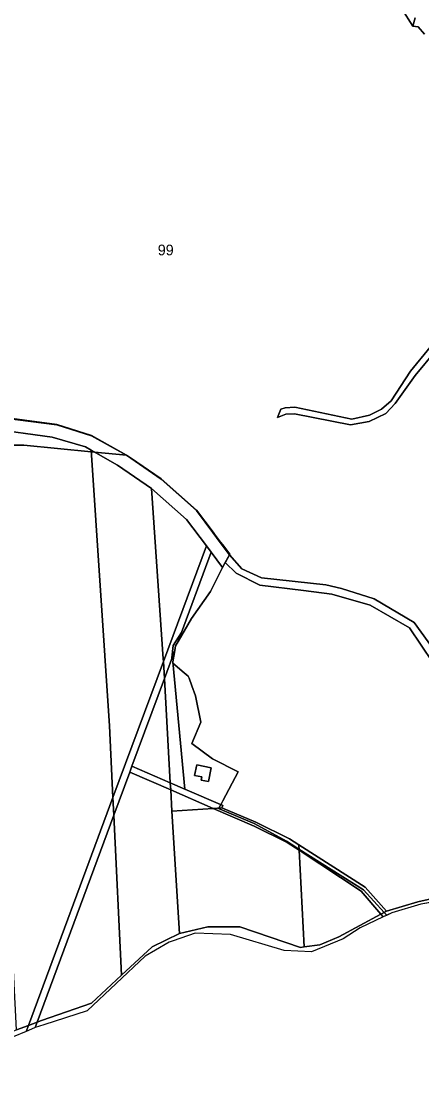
# Model space of a CAD drawing. Extents: x -522079 to -518833, y -1142400 to -1139961.
# Drawn here: x -519379.4 to -519191.9, y -1141869.9 to -1141371.1 of the extents above; entities that cross this region are included whole.
import ezdxf

# ---------------------------------------------------------------- set-up
doc = ezdxf.new("R2010")
doc.units = 0
for name, color, linetype in [('95560013', 7, 'Continuous'), ('95610013', 7, 'Continuous'), ('95620013', 7, 'Continuous'), ('95630013', 7, 'Continuous'), ('95640013', 7, 'Continuous'), ('95660013', 7, 'Continuous')]:
    doc.layers.add(name, color=color, linetype=linetype)

msp = doc.modelspace()

# ---------------------------------------------------------------- linework, layer by layer
at = {"layer": '95560013'}
for points in [[(-519338.11, -1141700.9), (-519336.47, -1141734.52), (-519376.07, -1141841.19), (-519381.7, -1141843.28), (-519389.39, -1141692.08), (-519397.82, -1141561.07), (-519394.67, -1141561.74), (-519364.95, -1141565.79), (-519349.35, -1141570.28), (-519346.66, -1141571.83)], [(-519312.91, -1141669.62), (-519312.84, -1141670.86), (-519336.47, -1141734.52), (-519338.11, -1141700.9), (-519346.66, -1141571.83), (-519334.38, -1141578.92), (-519318.43, -1141589.84)], [(-519318.43, -1141589.84), (-519301.98, -1141604.24), (-519292.71, -1141616.64), (-519312.84, -1141670.86), (-519312.91, -1141669.62)], [(-519305.24, -1141798.22), (-519318.06, -1141804.43), (-519332.42, -1141817.72), (-519336.07, -1141742.78), (-519328.61, -1141722.63), (-519309.44, -1141730.94), (-519308.88, -1141740.9)], [(-519289.52, -1141739.58), (-519308.88, -1141740.9), (-519309.44, -1141730.94)], [(-519254.9, -1141755.61), (-519249.34, -1141759.14), (-519246.92, -1141804.45), (-519248.63, -1141804.68), (-519277.03, -1141795.09), (-519292.12, -1141794.98), (-519305.24, -1141798.22), (-519308.88, -1141740.9), (-519289.52, -1141739.58), (-519270.39, -1141747.88)], [(-519336.07, -1141742.78), (-519332.42, -1141817.72), (-519346.6, -1141830.84), (-519369.96, -1141838.92), (-519371.92, -1141839.65)], [(-519220.27, -1141778.33), (-519211, -1141789.08), (-519230.77, -1141799.67), (-519239.54, -1141803.44), (-519246.92, -1141804.45), (-519249.34, -1141759.14)], [(-519243.51, -1141806.68), (-519256.37, -1141806.05), (-519281.47, -1141798.57), (-519297.93, -1141798.04), (-519308.25, -1141801.56), (-519310.14, -1141802.21), (-519316.53, -1141805.97), (-519321.4, -1141808.82), (-519348.63, -1141834.32), (-519368.78, -1141840.86), (-519372.86, -1141842.19), (-519371.92, -1141839.65), (-519369.96, -1141838.92), (-519346.6, -1141830.84), (-519332.42, -1141817.72), (-519318.06, -1141804.43), (-519305.24, -1141798.22), (-519292.12, -1141794.98), (-519277.03, -1141795.09), (-519248.63, -1141804.68), (-519246.92, -1141804.45), (-519239.54, -1141803.44), (-519230.77, -1141799.67), (-519211, -1141789.08), (-519209.88, -1141790.38), (-519220.64, -1141795.43), (-519228.74, -1141800.67)], [(-519389.29, -1141849.01), (-519391.5, -1141849.93), (-519408.1, -1141868.36), (-519409.46, -1141869.87), (-519458.26, -1141842.83), (-519448.38, -1141847.58), (-519430.66, -1141856.11), (-519410.94, -1141866.01), (-519388.28, -1141845.72), (-519381.7, -1141843.28), (-519376.07, -1141841.19), (-519377.1, -1141843.96)]]:
    msp.add_lwpolyline(points, close=True, dxfattribs=at)
at = {"layer": '95610013'}
for points in [[(-519290.49, -1141619.61), (-519285.15, -1141626.73), (-519290.81, -1141638.01), (-519299.72, -1141650.6), (-519305.95, -1141661.39)], [(-519308.5, -1141671.02), (-519302.86, -1141730.53), (-519309.63, -1141727.6), (-519312.39, -1141678.8), (-519307.53, -1141665.67)], [(-519309.63, -1141727.6), (-519327.57, -1141719.82), (-519312.39, -1141678.8)]]:
    msp.add_lwpolyline(points, close=True, dxfattribs=at)
at = {"layer": '95620013'}
for points in [[(-519201.22, -1141365.24), (-519195.98, -1141373.38), (-519193.48, -1141373.59), (-519190.53, -1141377.07)], [(-519187.98, -1141523.67), (-519197.16, -1141534.83), (-519206.19, -1141548.7), (-519210.78, -1141552.72), (-519216.28, -1141555.43), (-519224.64, -1141557.32), (-519251.3, -1141551.66), (-519255.9, -1141551.98), (-519257.81, -1141552.73), (-519259.41, -1141556.52), (-519255.57, -1141555.02), (-519251.39, -1141554.86), (-519225.22, -1141560.03), (-519216.52, -1141558.38), (-519208.65, -1141554.69), (-519204.3, -1141549.93), (-519194.87, -1141536.97), (-519185.11, -1141524.98)], [(-519185.55, -1141666.07), (-519195.4, -1141652.58), (-519214.22, -1141641.4), (-519229.49, -1141636.68), (-519236.73, -1141634.83), (-519266.93, -1141631.65), (-519276.07, -1141627.44), (-519281.83, -1141620.82), (-519286.19, -1141615.06), (-519289.76, -1141610.43), (-519297.36, -1141600.15), (-519313.9, -1141585.4), (-519330.14, -1141574.2), (-519346.5, -1141565.05), (-519362.75, -1141559.82), (-519393.2, -1141555.81)], [(-519181.21, -1141780.54), (-519193.63, -1141783.33), (-519208.31, -1141787.64), (-519218.36, -1141776.45), (-519249.47, -1141756.69), (-519253.85, -1141753.9), (-519269.54, -1141746.07), (-519285.49, -1141739.31), (-519284.96, -1141738.29), (-519302.86, -1141730.53), (-519308.5, -1141671.02), (-519307.53, -1141665.67), (-519307.13, -1141663.43), (-519305.95, -1141661.39), (-519299.72, -1141650.6), (-519290.81, -1141638.01), (-519285.15, -1141626.73), (-519283.88, -1141624.46), (-519278.79, -1141629.39), (-519267.72, -1141635.03), (-519247.24, -1141637.55), (-519234.03, -1141639.34), (-519215.97, -1141644.42), (-519197.57, -1141654.98), (-519170.28, -1141695.6)]]:
    msp.add_lwpolyline(points, dxfattribs=at)
msp.add_lwpolyline([(-519297.27, -1141719.22), (-519298.29, -1141724.1), (-519294.81, -1141724.84), (-519295.11, -1141726.32), (-519291.74, -1141727), (-519290.41, -1141720.65)], close=True, dxfattribs=at)
at = {"layer": '95630013'}
for points in [[(-519194.96, -1141369.43), (-519195.98, -1141373.38), (-519201.22, -1141365.24)], [(-519190.53, -1141377.07), (-519193.48, -1141373.59), (-519195.98, -1141373.38), (-519194.96, -1141369.43)]]:
    msp.add_lwpolyline(points, dxfattribs=at)
at = {"layer": '95640013'}
for points in [[(-519185.11, -1141524.98), (-519194.87, -1141536.97), (-519204.3, -1141549.93), (-519208.65, -1141554.69), (-519216.52, -1141558.38), (-519225.22, -1141560.03), (-519251.39, -1141554.86), (-519255.57, -1141555.02), (-519259.41, -1141556.52), (-519257.81, -1141552.73), (-519255.9, -1141551.98), (-519251.3, -1141551.66), (-519224.64, -1141557.32), (-519216.28, -1141555.43), (-519210.78, -1141552.72), (-519206.19, -1141548.7), (-519197.16, -1141534.83), (-519187.98, -1141523.67)], [(-519393.2, -1141555.81), (-519362.75, -1141559.82), (-519346.5, -1141565.05), (-519330.14, -1141574.2), (-519313.9, -1141585.4), (-519297.36, -1141600.15), (-519289.76, -1141610.43), (-519286.19, -1141615.06), (-519281.83, -1141620.82), (-519283.88, -1141624.46), (-519285.15, -1141626.73), (-519290.49, -1141619.61), (-519292.71, -1141616.64), (-519301.98, -1141604.24), (-519318.43, -1141589.84), (-519334.38, -1141578.92), (-519346.66, -1141571.83), (-519349.35, -1141570.28), (-519364.95, -1141565.79), (-519394.67, -1141561.74)]]:
    msp.add_lwpolyline(points, dxfattribs=at)
for points in [[(-519292.71, -1141616.64), (-519290.49, -1141619.61), (-519305.95, -1141661.39), (-519307.13, -1141663.43), (-519307.53, -1141665.67), (-519312.39, -1141678.8), (-519312.84, -1141670.86)], [(-519215.97, -1141644.42), (-519234.03, -1141639.34), (-519247.24, -1141637.55), (-519267.72, -1141635.03), (-519278.79, -1141629.39), (-519283.88, -1141624.46), (-519281.83, -1141620.82), (-519276.07, -1141627.44), (-519266.93, -1141631.65), (-519236.73, -1141634.83), (-519229.49, -1141636.68), (-519214.22, -1141641.4), (-519195.4, -1141652.58), (-519185.55, -1141666.07), (-519168.83, -1141692.07), (-519157.76, -1141703.36), (-519119.77, -1141724.36), (-519107.07, -1141732.42), (-519111.34, -1141734.71), (-519122.24, -1141726.88), (-519160.32, -1141706.01), (-519170.28, -1141695.6), (-519197.57, -1141654.98)], [(-519312.39, -1141678.8), (-519327.57, -1141719.82), (-519328.61, -1141722.63), (-519336.07, -1141742.78), (-519336.47, -1141734.52), (-519312.84, -1141670.86)], [(-519298.29, -1141724.1), (-519297.27, -1141719.22), (-519290.41, -1141720.65), (-519291.74, -1141727), (-519295.11, -1141726.32), (-519294.81, -1141724.84)], [(-519309.44, -1141730.94), (-519328.61, -1141722.63), (-519327.57, -1141719.82), (-519309.63, -1141727.6)], [(-519285.49, -1141739.31), (-519289.52, -1141739.58), (-519309.44, -1141730.94), (-519309.63, -1141727.6), (-519302.86, -1141730.53), (-519284.96, -1141738.29)], [(-519336.47, -1141734.52), (-519336.07, -1141742.78), (-519371.92, -1141839.65), (-519376.07, -1141841.19)], [(-519192.31, -1141784.44), (-519205.85, -1141788.49), (-519209.88, -1141790.38), (-519211, -1141789.08), (-519208.31, -1141787.64), (-519193.63, -1141783.33), (-519181.21, -1141780.54), (-519173.18, -1141777.23), (-519164.17, -1141772.59), (-519130.56, -1141747.22), (-519111.34, -1141734.71), (-519107.07, -1141732.42), (-519106.29, -1141740.33), (-519117.64, -1141741.85), (-519132.98, -1141750.7), (-519141.38, -1141757.45), (-519162.82, -1141773.79), (-519171.52, -1141778.29), (-519182.83, -1141782.69)], [(-519253.85, -1141753.9), (-519249.47, -1141756.69), (-519249.34, -1141759.14), (-519254.9, -1141755.61), (-519270.39, -1141747.88), (-519289.52, -1141739.58), (-519285.49, -1141739.31), (-519269.54, -1141746.07)], [(-519249.47, -1141756.69), (-519218.36, -1141776.45), (-519208.31, -1141787.64), (-519211, -1141789.08), (-519220.27, -1141778.33), (-519249.34, -1141759.14)], [(-519377.1, -1141843.96), (-519376.07, -1141841.19), (-519371.92, -1141839.65), (-519372.86, -1141842.19), (-519376.08, -1141843.54)]]:
    msp.add_lwpolyline(points, close=True, dxfattribs=at)
at = {"layer": '95660013'}
for points in [[(-519393.29, -1141556.08), (-519362.83, -1141559.96), (-519346.58, -1141565.12), (-519330.41, -1141574.07), (-519330.18, -1141574.2), (-519345.08, -1141572.74), (-519346.61, -1141572.59), (-519378.18, -1141569.49), (-519397.28, -1141569.49)], [(-519185.92, -1141783.26), (-519192.31, -1141784.44), (-519205.85, -1141788.49), (-519208.35, -1141789.66), (-519208.58, -1141789.26), (-519209.49, -1141788.27), (-519219.1, -1141777.78), (-519249.37, -1141758.61), (-519250.82, -1141757.69), (-519255.22, -1141754.92), (-519270.39, -1141746.69), (-519287.01, -1141739.67), (-519286.86, -1141739.4), (-519286.11, -1141738.02), (-519286.01, -1141737.83), (-519285.04, -1141736), (-519277.9, -1141722.39), (-519289.85, -1141716.31), (-519299.57, -1141709.24), (-519295.29, -1141699.2), (-519297.77, -1141686.8), (-519299.51, -1141682.18), (-519300.85, -1141678.61), (-519301.18, -1141677.74), (-519303.06, -1141676.16), (-519308.44, -1141671.65), (-519308.5, -1141671.02), (-519307.53, -1141665.67), (-519308.86, -1141669.27), (-519308.84, -1141669.03), (-519308.29, -1141663.27), (-519304.41, -1141657.24), (-519305.95, -1141661.39), (-519299.72, -1141650.6), (-519290.81, -1141638.01), (-519286.13, -1141628.69), (-519285, -1141626.52), (-519283.86, -1141624.48), (-519283.73, -1141624.25), (-519281.83, -1141620.82), (-519281.71, -1141620.6), (-519285.08, -1141616.18), (-519286.09, -1141614.85), (-519288.55, -1141611.63), (-519289.56, -1141610.31), (-519297.31, -1141600.01), (-519313.9, -1141585.33), (-519325.31, -1141577.53), (-519330.18, -1141574.2), (-519330.41, -1141574.07), (-519346.58, -1141565.12), (-519362.83, -1141559.96), (-519393.29, -1141556.08)], [(-519397.28, -1141569.49), (-519378.18, -1141569.49), (-519346.61, -1141572.59), (-519345.08, -1141572.74), (-519330.18, -1141574.2), (-519325.31, -1141577.53), (-519313.9, -1141585.33), (-519297.31, -1141600.01), (-519289.56, -1141610.31), (-519288.55, -1141611.63), (-519286.09, -1141614.85), (-519285.08, -1141616.18), (-519281.71, -1141620.6), (-519281.83, -1141620.82), (-519283.73, -1141624.25), (-519283.86, -1141624.48), (-519285, -1141626.52), (-519286.13, -1141628.69), (-519290.81, -1141638.01), (-519299.72, -1141650.6), (-519305.95, -1141661.39), (-519304.41, -1141657.24), (-519308.29, -1141663.27), (-519308.84, -1141669.03), (-519308.86, -1141669.27), (-519307.53, -1141665.67), (-519308.5, -1141671.02), (-519308.44, -1141671.65), (-519303.06, -1141676.16), (-519301.18, -1141677.74), (-519300.85, -1141678.61), (-519299.51, -1141682.18), (-519297.77, -1141686.8), (-519295.29, -1141699.2), (-519299.57, -1141709.24), (-519289.85, -1141716.31), (-519277.9, -1141722.39), (-519285.04, -1141736), (-519286.01, -1141737.83), (-519286.11, -1141738.02), (-519286.86, -1141739.4), (-519287.01, -1141739.67), (-519270.39, -1141746.69), (-519255.22, -1141754.92), (-519250.82, -1141757.69), (-519249.37, -1141758.61), (-519219.1, -1141777.78), (-519209.49, -1141788.27), (-519208.58, -1141789.26), (-519208.35, -1141789.66), (-519209.88, -1141790.38), (-519220.64, -1141795.43), (-519228.74, -1141800.67), (-519243.51, -1141806.68), (-519256.37, -1141806.05), (-519281.47, -1141798.57), (-519297.93, -1141798.04), (-519308.25, -1141801.56), (-519310.14, -1141802.21), (-519316.53, -1141805.97), (-519321.4, -1141808.82), (-519348.63, -1141834.32), (-519368.78, -1141840.86), (-519372.86, -1141842.19), (-519376.08, -1141843.54), (-519377.1, -1141843.96), (-519389.29, -1141849.01)]]:
    msp.add_lwpolyline(points, dxfattribs=at)

# ---------------------------------------------------------------- texts
msp.add_text('99', height=5, rotation=0, dxfattribs=at).set_placement((-519315.48, -1141480.63))

doc.saveas('drawing.dxf')
